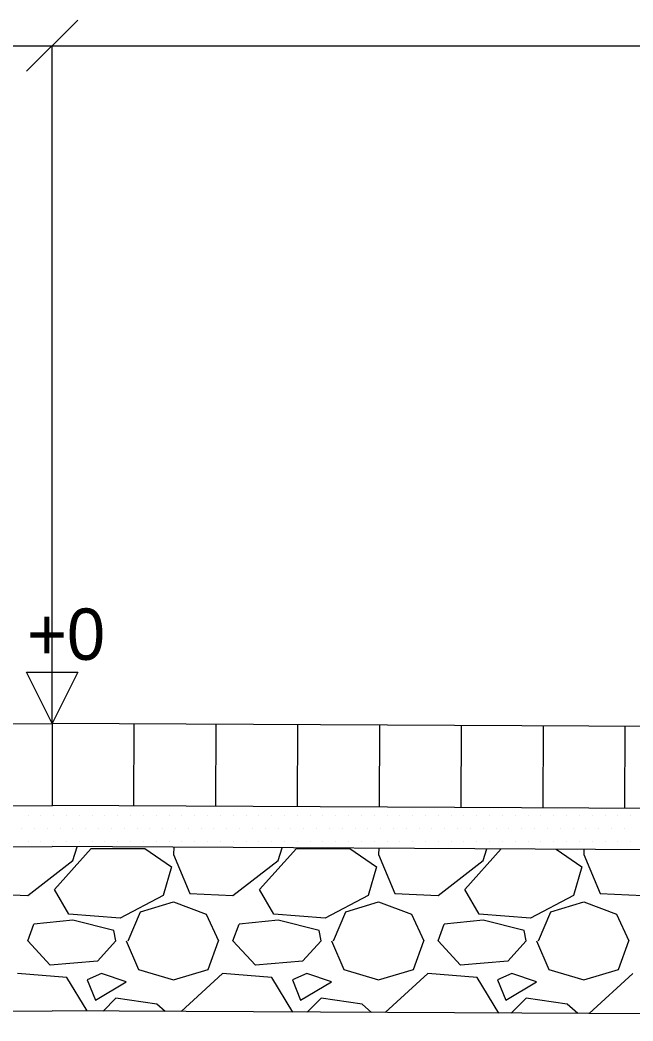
# Model space of a CAD drawing. Extents: x -219625893 to 7498339, y 5791790 to 5792761.
# Drawn here: x 7495413.67 to 7495428.61, y 5791866.2 to 5791890.59 of the extents above; entities that cross this region are included whole.
import ezdxf

# ---------------------------------------------------------------- set-up
doc = ezdxf.new("R2010")
doc.units = 0
for name, color, linetype in [('D_kons_wyp_podsypka_cem-piask', 7, 'Continuous'), ('D_kons_wyp_pospolka', 7, 'Continuous'), ('D_wymiary_500', 7, 'Continuous'), ('Level 1', 7, 'Continuous'), ('Level 10', 7, 'Continuous'), ('wymiary', 7, 'Continuous')]:
    doc.layers.add(name, color=color, linetype=linetype)

msp = doc.modelspace()

# ---------------------------------------------------------------- linework, layer by layer
at = {"layer": 'D_kons_wyp_podsypka_cem-piask'}
for p, q in [((7495413.869, 5791871.207), (7495413.869, 5791871.207)), ((7495414.182, 5791871.207), (7495414.182, 5791871.207)), ((7495414.494, 5791871.207), (7495414.494, 5791871.207)), ((7495414.807, 5791871.207), (7495414.807, 5791871.207)), ((7495415.119, 5791871.207), (7495415.119, 5791871.207)), ((7495415.432, 5791871.207), (7495415.432, 5791871.207)), ((7495415.744, 5791871.207), (7495415.744, 5791871.207)), ((7495416.057, 5791871.207), (7495416.057, 5791871.207)), ((7495416.369, 5791871.207), (7495416.369, 5791871.207)), ((7495416.682, 5791871.207), (7495416.682, 5791871.207)), ((7495416.994, 5791871.207), (7495416.994, 5791871.207)), ((7495417.307, 5791871.207), (7495417.307, 5791871.207)), ((7495417.619, 5791871.207), (7495417.619, 5791871.207)), ((7495417.932, 5791871.207), (7495417.932, 5791871.207)), ((7495418.244, 5791871.207), (7495418.244, 5791871.207)), ((7495418.557, 5791871.207), (7495418.557, 5791871.207)), ((7495418.869, 5791871.207), (7495418.869, 5791871.207)), ((7495419.182, 5791871.207), (7495419.182, 5791871.207)), ((7495419.494, 5791871.207), (7495419.494, 5791871.207)), ((7495419.807, 5791871.207), (7495419.807, 5791871.207)), ((7495420.119, 5791871.207), (7495420.119, 5791871.207)), ((7495420.432, 5791871.207), (7495420.432, 5791871.207)), ((7495420.744, 5791871.207), (7495420.744, 5791871.207)), ((7495421.057, 5791871.207), (7495421.057, 5791871.207)), ((7495421.369, 5791871.207), (7495421.369, 5791871.207)), ((7495421.682, 5791871.207), (7495421.682, 5791871.207)), ((7495421.994, 5791871.207), (7495421.994, 5791871.207)), ((7495422.307, 5791871.207), (7495422.307, 5791871.207)), ((7495422.619, 5791871.207), (7495422.619, 5791871.207)), ((7495422.932, 5791871.207), (7495422.932, 5791871.207)), ((7495423.244, 5791871.207), (7495423.244, 5791871.207)), ((7495423.557, 5791871.207), (7495423.557, 5791871.207)), ((7495423.869, 5791871.207), (7495423.869, 5791871.207)), ((7495424.182, 5791871.207), (7495424.182, 5791871.207)), ((7495424.494, 5791871.207), (7495424.494, 5791871.207)), ((7495424.807, 5791871.207), (7495424.807, 5791871.207)), ((7495425.119, 5791871.207), (7495425.119, 5791871.207)), ((7495425.432, 5791871.207), (7495425.432, 5791871.207)), ((7495425.744, 5791871.207), (7495425.744, 5791871.207)), ((7495426.057, 5791871.207), (7495426.057, 5791871.207)), ((7495426.369, 5791871.207), (7495426.369, 5791871.207)), ((7495426.682, 5791871.207), (7495426.682, 5791871.207)), ((7495426.994, 5791871.207), (7495426.994, 5791871.207)), ((7495427.307, 5791871.207), (7495427.307, 5791871.207)), ((7495427.619, 5791871.207), (7495427.619, 5791871.207)), ((7495427.932, 5791871.207), (7495427.932, 5791871.207)), ((7495428.244, 5791871.207), (7495428.244, 5791871.207)), ((7495428.557, 5791871.207), (7495428.557, 5791871.207)), ((7495413.713, 5791870.894), (7495413.713, 5791870.894)), ((7495414.026, 5791870.894), (7495414.026, 5791870.894)), ((7495414.338, 5791870.894), (7495414.338, 5791870.894)), ((7495414.651, 5791870.894), (7495414.651, 5791870.894)), ((7495414.963, 5791870.894), (7495414.963, 5791870.894)), ((7495415.276, 5791870.894), (7495415.276, 5791870.894)), ((7495415.588, 5791870.894), (7495415.588, 5791870.894)), ((7495415.901, 5791870.894), (7495415.901, 5791870.894)), ((7495416.213, 5791870.894), (7495416.213, 5791870.894)), ((7495416.526, 5791870.894), (7495416.526, 5791870.894)), ((7495416.838, 5791870.894), (7495416.838, 5791870.894)), ((7495417.151, 5791870.894), (7495417.151, 5791870.894)), ((7495417.463, 5791870.894), (7495417.463, 5791870.894)), ((7495417.776, 5791870.894), (7495417.776, 5791870.894)), ((7495418.088, 5791870.894), (7495418.088, 5791870.894)), ((7495418.401, 5791870.894), (7495418.401, 5791870.894)), ((7495418.713, 5791870.894), (7495418.713, 5791870.894)), ((7495419.026, 5791870.894), (7495419.026, 5791870.894)), ((7495419.338, 5791870.894), (7495419.338, 5791870.894)), ((7495419.651, 5791870.894), (7495419.651, 5791870.894)), ((7495419.963, 5791870.894), (7495419.963, 5791870.894)), ((7495420.276, 5791870.894), (7495420.276, 5791870.894)), ((7495420.588, 5791870.894), (7495420.588, 5791870.894)), ((7495420.901, 5791870.894), (7495420.901, 5791870.894)), ((7495421.213, 5791870.894), (7495421.213, 5791870.894)), ((7495421.526, 5791870.894), (7495421.526, 5791870.894)), ((7495421.838, 5791870.894), (7495421.838, 5791870.894)), ((7495422.151, 5791870.894), (7495422.151, 5791870.894)), ((7495422.463, 5791870.894), (7495422.463, 5791870.894)), ((7495422.776, 5791870.894), (7495422.776, 5791870.894)), ((7495423.088, 5791870.894), (7495423.088, 5791870.894)), ((7495423.401, 5791870.894), (7495423.401, 5791870.894)), ((7495423.713, 5791870.894), (7495423.713, 5791870.894)), ((7495424.026, 5791870.894), (7495424.026, 5791870.894)), ((7495424.338, 5791870.894), (7495424.338, 5791870.894)), ((7495424.651, 5791870.894), (7495424.651, 5791870.894)), ((7495424.963, 5791870.894), (7495424.963, 5791870.894)), ((7495425.276, 5791870.894), (7495425.276, 5791870.894)), ((7495425.588, 5791870.894), (7495425.588, 5791870.894)), ((7495425.901, 5791870.894), (7495425.901, 5791870.894)), ((7495426.213, 5791870.894), (7495426.213, 5791870.894)), ((7495426.526, 5791870.894), (7495426.526, 5791870.894)), ((7495426.838, 5791870.894), (7495426.838, 5791870.894)), ((7495427.151, 5791870.894), (7495427.151, 5791870.894)), ((7495427.463, 5791870.894), (7495427.463, 5791870.894)), ((7495427.776, 5791870.894), (7495427.776, 5791870.894)), ((7495428.088, 5791870.894), (7495428.088, 5791870.894)), ((7495428.401, 5791870.894), (7495428.401, 5791870.894)), ((7495413.869, 5791870.582), (7495413.869, 5791870.582)), ((7495414.182, 5791870.582), (7495414.182, 5791870.582)), ((7495414.494, 5791870.582), (7495414.494, 5791870.582)), ((7495414.807, 5791870.582), (7495414.807, 5791870.582)), ((7495415.119, 5791870.582), (7495415.119, 5791870.582)), ((7495415.432, 5791870.582), (7495415.432, 5791870.582)), ((7495415.744, 5791870.582), (7495415.744, 5791870.582)), ((7495416.057, 5791870.582), (7495416.057, 5791870.582)), ((7495416.369, 5791870.582), (7495416.369, 5791870.582)), ((7495416.682, 5791870.582), (7495416.682, 5791870.582)), ((7495416.994, 5791870.582), (7495416.994, 5791870.582)), ((7495417.307, 5791870.582), (7495417.307, 5791870.582)), ((7495417.619, 5791870.582), (7495417.619, 5791870.582)), ((7495417.932, 5791870.582), (7495417.932, 5791870.582)), ((7495418.244, 5791870.582), (7495418.244, 5791870.582)), ((7495418.557, 5791870.582), (7495418.557, 5791870.582)), ((7495418.869, 5791870.582), (7495418.869, 5791870.582)), ((7495419.182, 5791870.582), (7495419.182, 5791870.582)), ((7495419.494, 5791870.582), (7495419.494, 5791870.582)), ((7495419.807, 5791870.582), (7495419.807, 5791870.582)), ((7495420.119, 5791870.582), (7495420.119, 5791870.582)), ((7495420.432, 5791870.582), (7495420.432, 5791870.582)), ((7495420.744, 5791870.582), (7495420.744, 5791870.582)), ((7495421.057, 5791870.582), (7495421.057, 5791870.582)), ((7495421.369, 5791870.582), (7495421.369, 5791870.582)), ((7495421.682, 5791870.582), (7495421.682, 5791870.582)), ((7495421.994, 5791870.582), (7495421.994, 5791870.582)), ((7495422.307, 5791870.582), (7495422.307, 5791870.582)), ((7495422.619, 5791870.582), (7495422.619, 5791870.582)), ((7495422.932, 5791870.582), (7495422.932, 5791870.582)), ((7495423.244, 5791870.582), (7495423.244, 5791870.582)), ((7495423.557, 5791870.582), (7495423.557, 5791870.582)), ((7495423.869, 5791870.582), (7495423.869, 5791870.582)), ((7495424.182, 5791870.582), (7495424.182, 5791870.582)), ((7495424.494, 5791870.582), (7495424.494, 5791870.582)), ((7495424.807, 5791870.582), (7495424.807, 5791870.582)), ((7495425.119, 5791870.582), (7495425.119, 5791870.582)), ((7495425.432, 5791870.582), (7495425.432, 5791870.582)), ((7495425.744, 5791870.582), (7495425.744, 5791870.582)), ((7495426.057, 5791870.582), (7495426.057, 5791870.582)), ((7495426.369, 5791870.582), (7495426.369, 5791870.582)), ((7495426.682, 5791870.582), (7495426.682, 5791870.582)), ((7495426.994, 5791870.582), (7495426.994, 5791870.582)), ((7495427.307, 5791870.582), (7495427.307, 5791870.582)), ((7495427.619, 5791870.582), (7495427.619, 5791870.582)), ((7495427.932, 5791870.582), (7495427.932, 5791870.582)), ((7495428.244, 5791870.582), (7495428.244, 5791870.582)), ((7495428.557, 5791870.582), (7495428.557, 5791870.582))]:
    msp.add_line(p, q, dxfattribs=at)
at = {"layer": 'D_kons_wyp_pospolka'}
for p, q in [((7495414.512, 5791869.411), (7495415.412, 5791870.411)), ((7495414.962, 5791870.111), (7495415.07, 5791870.449)), ((7495415.412, 5791870.411), (7495416.712, 5791870.411)), ((7495416.712, 5791870.411), (7495417.362, 5791869.961)), ((7495417.421, 5791870.437), (7495417.412, 5791870.261)), ((7495419.512, 5791869.411), (7495420.412, 5791870.411)), ((7495419.962, 5791870.111), (7495420.062, 5791870.424)), ((7495420.412, 5791870.411), (7495421.712, 5791870.411)), ((7495421.712, 5791870.411), (7495422.362, 5791869.961)), ((7495422.419, 5791870.412), (7495422.412, 5791870.261)), ((7495417.412, 5791870.261), (7495417.812, 5791869.311)), ((7495422.412, 5791870.261), (7495422.812, 5791869.311)), ((7495424.512, 5791869.411), (7495425.4, 5791870.397)), ((7495424.962, 5791870.111), (7495425.054, 5791870.399)), ((7495426.742, 5791870.39), (7495427.362, 5791869.961)), ((7495427.418, 5791870.387), (7495427.412, 5791870.261)), ((7495427.412, 5791870.261), (7495427.812, 5791869.311)), ((7495413.862, 5791869.261), (7495414.962, 5791870.111)), ((7495417.362, 5791869.961), (7495417.162, 5791869.261)), ((7495418.862, 5791869.261), (7495419.962, 5791870.111)), ((7495422.362, 5791869.961), (7495422.162, 5791869.261)), ((7495423.862, 5791869.261), (7495424.962, 5791870.111)), ((7495427.362, 5791869.961), (7495427.162, 5791869.261)), ((7495412.812, 5791869.311), (7495413.862, 5791869.261)), ((7495414.862, 5791868.811), (7495414.512, 5791869.411)), ((7495417.162, 5791869.261), (7495416.112, 5791868.711)), ((7495417.812, 5791869.311), (7495418.862, 5791869.261)), ((7495419.862, 5791868.811), (7495419.512, 5791869.411)), ((7495422.162, 5791869.261), (7495421.112, 5791868.711)), ((7495422.812, 5791869.311), (7495423.862, 5791869.261)), ((7495424.862, 5791868.811), (7495424.512, 5791869.411)), ((7495427.162, 5791869.261), (7495426.112, 5791868.711)), ((7495427.812, 5791869.311), (7495428.862, 5791869.261)), ((7495416.612, 5791868.861), (7495417.412, 5791869.111)), ((7495417.412, 5791869.111), (7495418.212, 5791868.811)), ((7495421.612, 5791868.861), (7495422.412, 5791869.111)), ((7495422.412, 5791869.111), (7495423.212, 5791868.811)), ((7495426.612, 5791868.861), (7495427.412, 5791869.111)), ((7495427.412, 5791869.111), (7495428.212, 5791868.811)), ((7495416.112, 5791868.711), (7495414.862, 5791868.811)), ((7495416.312, 5791868.161), (7495416.612, 5791868.861)), ((7495418.212, 5791868.811), (7495418.512, 5791868.161)), ((7495421.112, 5791868.711), (7495419.862, 5791868.811)), ((7495421.312, 5791868.161), (7495421.612, 5791868.861)), ((7495423.212, 5791868.811), (7495423.512, 5791868.161)), ((7495426.112, 5791868.711), (7495424.862, 5791868.811)), ((7495426.312, 5791868.161), (7495426.612, 5791868.861)), ((7495428.212, 5791868.811), (7495428.512, 5791868.161)), ((7495413.862, 5791868.161), (7495414.012, 5791868.561)), ((7495414.962, 5791868.661), (7495414.012, 5791868.561)), ((7495415.962, 5791868.411), (7495414.962, 5791868.661)), ((7495418.862, 5791868.161), (7495419.012, 5791868.561)), ((7495419.962, 5791868.661), (7495419.012, 5791868.561)), ((7495420.962, 5791868.411), (7495419.962, 5791868.661)), ((7495423.862, 5791868.161), (7495424.012, 5791868.561)), ((7495424.962, 5791868.661), (7495424.012, 5791868.561)), ((7495425.962, 5791868.411), (7495424.962, 5791868.661)), ((7495416.012, 5791868.161), (7495415.962, 5791868.411)), ((7495421.012, 5791868.161), (7495420.962, 5791868.411)), ((7495426.012, 5791868.161), (7495425.962, 5791868.411)), ((7495414.412, 5791867.561), (7495413.862, 5791868.161)), ((7495416.012, 5791868.161), (7495415.562, 5791867.661)), ((7495416.262, 5791868.161), (7495416.562, 5791867.461)), ((7495418.262, 5791867.461), (7495418.512, 5791868.161)), ((7495419.412, 5791867.561), (7495418.862, 5791868.161)), ((7495421.012, 5791868.161), (7495420.562, 5791867.661)), ((7495421.262, 5791868.161), (7495421.562, 5791867.461)), ((7495423.262, 5791867.461), (7495423.512, 5791868.161)), ((7495424.412, 5791867.561), (7495423.862, 5791868.161)), ((7495426.012, 5791868.161), (7495425.562, 5791867.661)), ((7495426.262, 5791868.161), (7495426.562, 5791867.461)), ((7495428.262, 5791867.461), (7495428.512, 5791868.161)), ((7495415.562, 5791867.661), (7495414.412, 5791867.561)), ((7495420.562, 5791867.661), (7495419.412, 5791867.561)), ((7495425.562, 5791867.661), (7495424.412, 5791867.561)), ((7495414.812, 5791867.261), (7495413.612, 5791867.361)), ((7495415.309, 5791866.448), (7495414.812, 5791867.261)), ((7495415.662, 5791867.361), (7495415.312, 5791867.211)), ((7495416.262, 5791867.161), (7495415.662, 5791867.361)), ((7495416.562, 5791867.461), (7495417.412, 5791867.211)), ((7495417.412, 5791867.211), (7495418.262, 5791867.461)), ((7495418.612, 5791867.361), (7495417.599, 5791866.436)), ((7495419.812, 5791867.261), (7495418.612, 5791867.361)), ((7495420.324, 5791866.423), (7495419.812, 5791867.261)), ((7495420.662, 5791867.361), (7495420.312, 5791867.211)), ((7495421.262, 5791867.161), (7495420.662, 5791867.361)), ((7495421.562, 5791867.461), (7495422.412, 5791867.211)), ((7495422.412, 5791867.211), (7495423.262, 5791867.461)), ((7495423.612, 5791867.361), (7495422.572, 5791866.411)), ((7495424.812, 5791867.261), (7495423.612, 5791867.361)), ((7495425.34, 5791866.397), (7495424.812, 5791867.261)), ((7495425.662, 5791867.361), (7495425.312, 5791867.211)), ((7495426.262, 5791867.161), (7495425.662, 5791867.361)), ((7495426.562, 5791867.461), (7495427.412, 5791867.211)), ((7495427.412, 5791867.211), (7495428.262, 5791867.461)), ((7495428.612, 5791867.361), (7495427.545, 5791866.386)), ((7495415.312, 5791867.211), (7495415.512, 5791866.711)), ((7495415.512, 5791866.711), (7495416.262, 5791867.161)), ((7495420.312, 5791867.211), (7495420.512, 5791866.711)), ((7495420.512, 5791866.711), (7495421.262, 5791867.161)), ((7495425.312, 5791867.211), (7495425.512, 5791866.711)), ((7495425.512, 5791866.711), (7495426.262, 5791867.161)), ((7495416.012, 5791866.761), (7495415.697, 5791866.446)), ((7495417.012, 5791866.611), (7495416.012, 5791866.761)), ((7495421.012, 5791866.761), (7495420.672, 5791866.421)), ((7495422.012, 5791866.611), (7495421.012, 5791866.761)), ((7495426.012, 5791866.761), (7495425.647, 5791866.396)), ((7495427.012, 5791866.611), (7495426.012, 5791866.761)), ((7495417.21, 5791866.438), (7495417.012, 5791866.611)), ((7495422.239, 5791866.413), (7495422.012, 5791866.611)), ((7495427.267, 5791866.388), (7495427.012, 5791866.611))]:
    msp.add_line(p, q, dxfattribs=at)
at = {"layer": 'D_wymiary_500'}
for p, q in [((7495415.083, 5791890.592), (7495413.833, 5791889.342)), ((7495198.458, 5791889.967), (7495494.458, 5791889.967)), ((7495414.458, 5791873.452), (7495414.458, 5791889.967)), ((7495364.458, 5791870.202), (7495414.458, 5791870.452)), ((7495464.445, 5791870.202), (7495414.458, 5791870.452)), ((7495365.053, 5791866.205), (7495414.458, 5791866.452)), ((7495463.458, 5791866.207), (7495414.458, 5791866.452))]:
    msp.add_line(p, q, dxfattribs=at)
at = {"layer": 'Level 1'}
for p, q in [((7495414.458, 5791873.452), (7495413.834, 5791874.702)), ((7495413.834, 5791874.702), (7495415.084, 5791874.701)), ((7495415.084, 5791874.701), (7495414.458, 5791873.452))]:
    msp.add_line(p, q, dxfattribs=at)
at = {"layer": 'Level 10'}
for p, q in [((7495363.961, 5791873.199), (7495414.458, 5791873.452)), ((7495464.458, 5791873.202), (7495414.458, 5791873.452)), ((7495414.458, 5791873.452), (7495414.458, 5791871.452)), ((7495416.45, 5791871.442), (7495416.46, 5791873.454)), ((7495418.444, 5791871.432), (7495418.454, 5791873.444)), ((7495420.438, 5791871.422), (7495420.448, 5791873.434)), ((7495422.432, 5791871.412), (7495422.443, 5791873.424)), ((7495424.427, 5791871.402), (7495424.437, 5791873.414)), ((7495426.421, 5791871.392), (7495426.431, 5791873.404)), ((7495428.415, 5791871.382), (7495428.425, 5791873.394)), ((7495364.361, 5791871.201), (7495414.466, 5791871.452)), ((7495464.45, 5791871.202), (7495414.45, 5791871.452))]:
    msp.add_line(p, q, dxfattribs=at)

# ---------------------------------------------------------------- texts
at = {"layer": 'wymiary'}
msp.add_text('+0', height=1.25, rotation=359.9571, dxfattribs=at).set_placement((7495413.841, 5791875.005))

doc.saveas('drawing.dxf')
